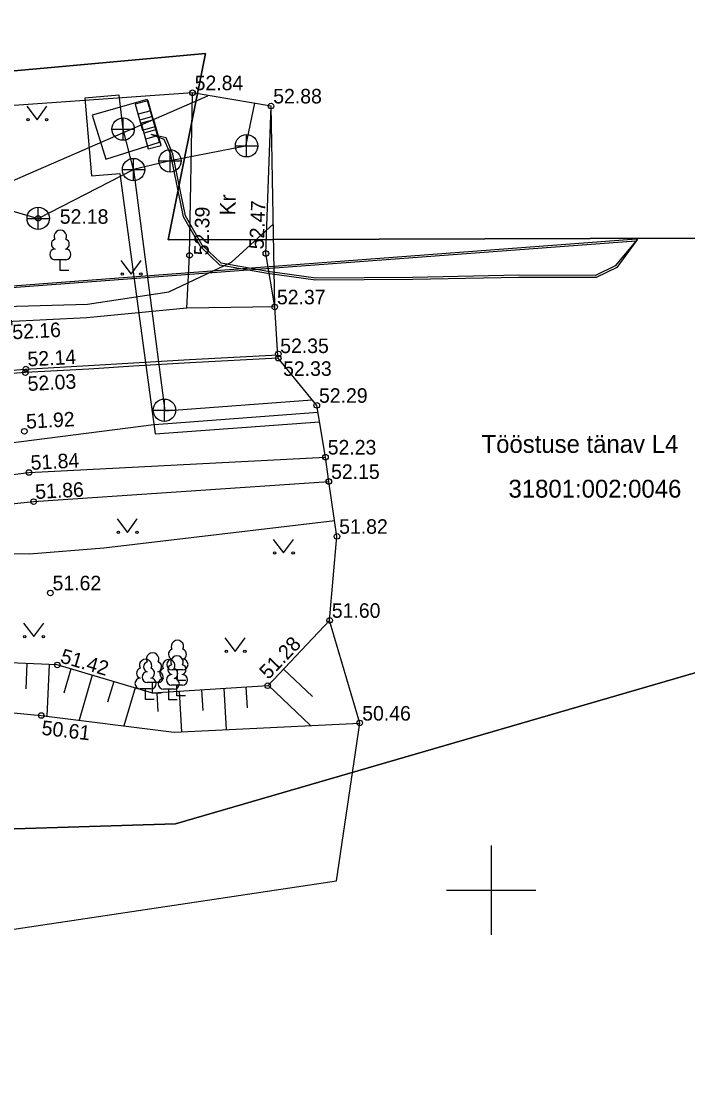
# Model space of a CAD drawing. Extents: x 542320 to 543602, y 6558748 to 6559969.
# Drawn here: x 543078.97 to 543108.8, y 6559791.38 to 6559838.87 of the extents above; entities that cross this region are included whole.
import ezdxf

# ---------------------------------------------------------------- set-up
doc = ezdxf.new("R2010")
doc.units = 0
for name, color, linetype in [('ELRAJATISMP', 7, 'Continuous'), ('HALJASTUS', 7, 'Continuous'), ('KKAEV', 7, 'Continuous'), ('KORGUS-EH2000', 7, 'Continuous'), ('KTRASS', 7, 'Continuous'), ('mootpiir', 7, 'Continuous'), ('MPKAABEL', 7, 'Continuous'), ('MPOHULIIN', 7, 'Continuous'), ('PIIR', 7, 'Continuous'), ('PUU', 7, 'Continuous'), ('RELJEEF', 7, 'Continuous'), ('SIOHULIIN', 7, 'Continuous'), ('SITRASS', 7, 'Continuous'), ('TEE', 7, 'Continuous'), ('VEEKOGU', 7, 'Continuous'), ('VORK', 7, 'Continuous'), ('VTRASS', 7, 'Continuous')]:
    doc.layers.add(name, color=color, linetype=linetype)

# ---------------------------------------------------------------- blocks, each defined once
blk = doc.blocks.new('VKORIS')
for p, q in [((0, 4), (0, -4)), ((-4, 0), (4, 0))]:
    blk.add_line(p, q)
blk = doc.blocks.new('KAKAEV')
for p, q in [((0, -1), (0, 1)), ((-1, 0), (1, 0))]:
    blk.add_line(p, q)
blk.add_circle((0, 0), 1)
blk = doc.blocks.new('LEHTP1')
for p, q in [((0.48, 0.95), (-0.48, 0.95)), ((0, 0), (0, 0.95)), ((0.76, 0), (0, 0))]:
    blk.add_line(p, q)
for centre, radius, start, end in [((0, 3.04), 0.554, 332.5799, 207.4201), ((-0.475, 1.425), 0.475, 90.0016, 269.3953), ((-0.34, 2.345), 0.465, 109.02174, 253.14154), ((0.34, 2.345), 0.465, 286.85082, 70.98591), ((0.475, 1.425), 0.475, 270.6047, 89.9984)]:
    blk.add_arc(centre, radius, start, end)
blk = doc.blocks.new('MURU')
for p, q in [((-0.927, 1.213), (0, 0)), ((0, 0), (0.891, 1.213))]:
    blk.add_line(p, q)
for centre in [(-0.802, 0), (0.856, 0)]:
    blk.add_circle(centre, 0.11)
blk = doc.blocks.new('ELKAPP')
for p, q in [((1.195, 0.597), (-1.195, 0.597)), ((-1.195, 0.597), (-1.195, -0.597)), ((-0.271, 0.597), (-0.271, -0.597)), ((0.271, 0.597), (0.271, -0.597)), ((1.195, -0.597), (1.195, 0.597)), ((-1.195, -0.597), (1.195, -0.597))]:
    blk.add_line(p, q)
blk = doc.blocks.new('RING02')
blk.add_circle((0, 0), 0.25)

msp = doc.modelspace()

# ---------------------------------------------------------------- linework, layer by layer
at = {"layer": 'KTRASS'}
for points in [[(543083.528, 6559834.046), (543083.349, 6559835.564), (543081.823, 6559835.431), (543082.115, 6559831.951), (543083.389, 6559832.057), (543084.964, 6559820.411), (543092.319, 6559820.95)], [(543089.402, 6559835.202), (543089.01, 6559833.277)], [(543066.724, 6559833.829), (543079.729, 6559830.052), (543083.997, 6559832.232)], [(543083.997, 6559832.232), (543083.528, 6559834.046)], [(543089.01, 6559833.277), (543085.628, 6559832.625)], [(543085.628, 6559832.625), (543083.997, 6559832.232)], [(543083.997, 6559832.232), (543085.402, 6559821.439)], [(543085.402, 6559821.439), (543091.987, 6559821.939)]]:
    msp.add_lwpolyline(points, dxfattribs=at)
at = {"layer": 'mootpiir'}
msp.add_lwpolyline([(543090.147, 6559835.076), (543086.631, 6559835.669), (543046.075, 6559832.791), (542960.087, 6559816.316), (542958.508, 6559813.972), (542958.352, 6559813.615), (542958.072, 6559811.407), (542958.097, 6559811.262), (542958.667, 6559807.427), (542958.816, 6559803.633), (542958.4, 6559802.481), (542958.245, 6559799.726), (542966.032, 6559797.567), (543032.743, 6559791.379), (543093.076, 6559800.414), (543094.129, 6559807.466), (543092.769, 6559812.064), (543093.098, 6559815.823), (543092.736, 6559818.278), (543092.585, 6559819.369), (543092.195, 6559821.683), (543090.475, 6559823.796), (543090.459, 6559823.908), (543090.312, 6559826.089)], close=True, dxfattribs=at)
at = {"layer": 'MPKAABEL'}
for points in [[(543106.54, 6559829.12), (543105.62, 6559827.85), (543104.69, 6559827.4), (543101.23, 6559827.41), (543096.5, 6559827.31), (543092.14, 6559827.28), (543089.99, 6559827.58), (543087.86, 6559827.95), (543086.99, 6559828.79), (543086.23, 6559830.12), (543085.66, 6559832.9), (543085.37, 6559833.58), (543084.79, 6559833.81)], [(543106.54, 6559829.12), (543105.55, 6559827.93), (543104.67, 6559827.5), (543101.23, 6559827.51), (543096.5, 6559827.41), (543092.15, 6559827.38), (543090.01, 6559827.68), (543087.91, 6559828.04), (543087.07, 6559828.85), (543086.32, 6559830.16), (543085.76, 6559832.93), (543085.45, 6559833.66), (543084.79, 6559833.81)]]:
    msp.add_lwpolyline(points, dxfattribs=at)
at = {"layer": 'MPOHULIIN'}
msp.add_lwpolyline([(543065.505, 6559826.048), (543106.507, 6559829.132)], dxfattribs=at)
at = {"layer": 'PIIR'}
for points in [[(543109.13, 6559904.85), (543125.66, 6559869.87), (543123.8, 6559868.51), (543128.91, 6559853.92), (543128.04, 6559829.23), (543085.54, 6559829.09), (543087.22, 6559837.42), (543076.83, 6559836.49), (543069.03, 6559887.03), (543109.13, 6559904.85)], [(543110.35, 6559810.08), (543085.87, 6559802.96), (543074.33, 6559802.6), (543047.65, 6559805.6), (543029.51, 6559799.26), (543012.82, 6559798.86), (543001.44, 6559800.31), (542966.22, 6559801.72), (542946.49, 6559799.49), (542945.79, 6559811), (542995.62, 6559810.72), (543011.79, 6559810.61), (543078.56, 6559825.31), (543076.83, 6559836.49), (543087.22, 6559837.42), (543085.54, 6559829.09), (543128.04, 6559829.23)], [(543012.82, 6559798.86), (543029.51, 6559799.26), (543047.65, 6559805.6), (543074.33, 6559802.6), (543085.87, 6559802.96), (543110.35, 6559810.08)]]:
    msp.add_lwpolyline(points, dxfattribs=at)
at = {"layer": 'RELJEEF'}
for points in [[(543092.769, 6559812.064), (543089.999, 6559809.142), (543084.85, 6559808.813), (543080.585, 6559810.073), (543073.543, 6559810.368), (543068.572, 6559810.695), (543059.132, 6559808.528), (543057.697, 6559808.874), (543055.711, 6559810.294), (543052.162, 6559811.058), (543042.149, 6559807.07), (543028.907, 6559800.786), (543017.173, 6559800.875), (543003.671, 6559801.671), (542989.215, 6559802.013), (542980.978, 6559802.587), (542969.167, 6559801.941), (542958.4, 6559802.481)], [(543079.219, 6559810.13), (543079.172, 6559809.006)], [(543080.218, 6559810.088), (543080.122, 6559807.778)], [(543081.192, 6559809.894), (543080.872, 6559808.809)], [(543090.705, 6559809.887), (543092.003, 6559808.656)], [(543082.151, 6559809.61), (543081.557, 6559807.598)], [(543083.11, 6559809.327), (543082.836, 6559808.399)], [(543084.069, 6559809.044), (543083.568, 6559807.346)], [(543086.033, 6559808.889), (543086.149, 6559807.08)], [(543087.031, 6559808.952), (543087.09, 6559808.04)], [(543088.029, 6559809.016), (543088.147, 6559807.177)], [(543089.027, 6559809.08), (543089.087, 6559808.152)], [(543090.017, 6559809.161), (543091.918, 6559807.359)], [(543085.035, 6559808.825), (543085.089, 6559807.986)]]:
    msp.add_lwpolyline(points, dxfattribs=at)
at = {"layer": 'SIOHULIIN'}
for points in [[(542986.521, 6559827.98), (543065.505, 6559826.048), (543087.322, 6559835.539)], [(543065.564, 6559825.995), (543106.476, 6559829.043)]]:
    msp.add_lwpolyline(points, dxfattribs=at)
at = {"layer": 'SITRASS'}
for points in [[(543053.917, 6559829.286), (543053.974, 6559828.4), (543059.028, 6559827.021), (543065.55, 6559826.599), (543077.169, 6559826.084), (543081.941, 6559826.218), (543085.572, 6559826.758), (543088.386, 6559828.092), (543090.244, 6559829.795)], [(543078.354, 6559815.059), (543079.334, 6559815.049), (543082.664, 6559815.311), (543092.997, 6559816.527)]]:
    msp.add_lwpolyline(points, dxfattribs=at)
at = {"layer": 'TEE'}
for points in [[(543086.383, 6559826.03), (543086.502, 6559828.397), (543086.631, 6559835.669)], [(543082.751, 6559832.699), (543085.159, 6559833.466), (543084.609, 6559835.363), (543082.149, 6559834.671), (543082.751, 6559832.699)], [(543090.312, 6559826.089), (543089.919, 6559828.48), (543090.147, 6559835.076)], [(543090.312, 6559826.089), (543086.383, 6559826.03), (543081.905, 6559825.596), (543078.303, 6559825.425), (543074.1, 6559825.199), (543070.074, 6559824.663), (543067.487, 6559824.275), (543065.214, 6559823.846), (543059.834, 6559822.98), (543060.342, 6559820.61)], [(543090.467, 6559823.936), (543086.5, 6559823.721), (543083.992, 6559823.574), (543081.981, 6559823.449), (543079.149, 6559823.293), (543078.382, 6559823.232), (543074.353, 6559822.916), (543070.335, 6559822.452), (543067.933, 6559822.071), (543065.56, 6559821.631), (543060.801, 6559820.746), (543060.324, 6559820.64)], [(543090.475, 6559823.796), (543086.508, 6559823.581), (543084, 6559823.434), (543081.989, 6559823.309), (543079.158, 6559823.153), (543078.393, 6559823.092), (543074.367, 6559822.777), (543070.354, 6559822.313), (543067.957, 6559821.933), (543065.586, 6559821.493), (543060.829, 6559820.609), (543060.355, 6559820.503)], [(542958.816, 6559803.633), (542969.162, 6559804.651), (542980.925, 6559804.056), (542987.926, 6559803.597), (542997.513, 6559803.059), (543007.107, 6559803.04), (543017.723, 6559803.474), (543028.051, 6559804.793), (543037.828, 6559808.06), (543042.163, 6559809.918), (543050.261, 6559812.635), (543059.043, 6559815.346), (543068.835, 6559817.386), (543079.318, 6559818.681), (543092.585, 6559819.369)], [(542997.513, 6559803.059), (543007.066, 6559802.483), (543017.906, 6559802.775), (543028.213, 6559804.2), (543038.057, 6559807.69), (543042.598, 6559809.18), (543050.432, 6559811.965), (543059.255, 6559814.566), (543068.982, 6559816.272), (543079.524, 6559817.38), (543092.736, 6559818.278)]]:
    msp.add_lwpolyline(points, dxfattribs=at)
at = {"layer": 'VEEKOGU'}
msp.add_lwpolyline([(542958.245, 6559799.726), (542969.193, 6559799.837), (542980.767, 6559800.499), (542989.253, 6559800.672), (543003.747, 6559800.309), (543017.23, 6559799.73), (543028.875, 6559799.639), (543042.762, 6559805.872), (543054.415, 6559808.402), (543057.212, 6559806.164), (543069.386, 6559808.821), (543079.867, 6559807.81), (543085.814, 6559807.064), (543094.129, 6559807.466)], dxfattribs=at)
at = {"layer": 'VTRASS'}
for points in [[(543092.248, 6559821.369), (543084.938, 6559820.819), (543084.909, 6559820.815)], [(543084.909, 6559820.815), (543050.322, 6559816.388), (543018.303, 6559809.334), (542995.998, 6559810.646), (542958.256, 6559810.221)]]:
    msp.add_lwpolyline(points, dxfattribs=at)

# ---------------------------------------------------------------- block references
at = {"layer": 'ELRAJATISMP', "xscale": 0.5, "yscale": 0.5, "rotation": -74.41800004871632}
for p in [(543084.522, 6559834.658), (543084.782, 6559833.81)]:
    msp.add_blockref('ELKAPP', p, dxfattribs=at)
at = {"layer": 'HALJASTUS', "xscale": 0.5, "yscale": 0.5}
for p in [(543079.678, 6559834.464), (543083.895, 6559827.561), (543083.72, 6559816.004), (543090.71, 6559815.083), (543079.529, 6559811.338), (543088.549, 6559810.677)]:
    msp.add_blockref('MURU', p, dxfattribs=at)
at = {"layer": 'KKAEV', "xscale": 0.5, "yscale": 0.5}
for p in [(543083.528, 6559834.046), (543089.054, 6559833.298), (543085.628, 6559832.625), (543083.997, 6559832.232), (543079.729, 6559830.052), (543085.377, 6559821.468)]:
    msp.add_blockref('KAKAEV', p, dxfattribs=at)
at = {"layer": 'KORGUS-EH2000', "xscale": 0.5, "yscale": 0.5}
for p in [(543086.631, 6559835.669), (543090.147, 6559835.076), (543079.729, 6559830.052), (543086.502, 6559828.397), (543089.919, 6559828.48), (543090.312, 6559826.089), (543090.475, 6559823.985), (543090.475, 6559823.796), (543079.158, 6559823.153), (543079.18, 6559823.311), (543092.195, 6559821.683), (543079.113, 6559820.525), (543092.585, 6559819.369), (543079.318, 6559818.681), (543092.736, 6559818.278), (543079.524, 6559817.38), (543093.098, 6559815.823), (543080.273, 6559813.294), (543092.769, 6559812.064), (543080.585, 6559810.073), (543089.999, 6559809.142), (543079.867, 6559807.81), (543094.114, 6559807.477)]:
    msp.add_blockref('RING02', p, dxfattribs=at)
at = {"layer": 'PUU', "xscale": 0.5, "yscale": 0.5}
for p in [(543080.72, 6559827.725), (543085.959, 6559809.378), (543084.535, 6559808.528), (543084.85, 6559808.813), (543085.572, 6559808.514), (543085.94, 6559808.689)]:
    msp.add_blockref('LEHTP1', p, dxfattribs=at)
at = {"layer": 'VORK', "xscale": 0.5, "yscale": 0.5}
msp.add_blockref('VKORIS', (543100, 6559800), dxfattribs=at)

# ---------------------------------------------------------------- texts
at = {"layer": 'KORGUS-EH2000'}
for s, p in [('52.84', (543086.731, 6559835.786)), ('52.88', (543090.247, 6559835.193)), ('52.18', (543080.697, 6559829.808)), ('52.37', (543090.412, 6559826.206)), ('52.35', (543090.559, 6559824.025)), ('52.33', (543090.688, 6559823.005)), ('52.29', (543092.295, 6559821.8)), ('52.23', (543092.685, 6559819.486)), ('52.15', (543092.836, 6559818.395)), ('51.82', (543093.198, 6559815.94)), ('51.62', (543080.373, 6559813.411)), ('51.60', (543092.869, 6559812.181)), ('50.46', (543094.229, 6559807.583))]:
    msp.add_text(s, height=0.65, dxfattribs=at).set_placement(p)
for s, rotation, p in [('52.47', 87.5335, (543089.817, 6559828.656)), ('52.39', 88.6145, (543087.353, 6559828.39)), ('52.16', 2.9274, (543078.587, 6559824.64)), ('52.14', 2.9274, (543079.269, 6559823.427)), ('52.03', 2.9274, (543079.273, 6559822.328)), ('51.92', 2.9274, (543079.202, 6559820.641)), ('51.84', 2.9274, (543079.407, 6559818.797)), ('51.86', 2.9274, (543079.613, 6559817.496)), ('51.28', 46.231, (543090.03, 6559809.389)), ('51.42', 343.6293, (543080.68, 6559810.19)), ('50.61', 353.2479, (543079.857, 6559806.952))]:
    msp.add_text(s, height=0.65, rotation=rotation, dxfattribs=at).set_placement(p)
at = {"layer": 'PIIR'}
for s, p in [('Tööstuse tänav L4', (543099.569, 6559819.559)), ('31801:002:0046', (543100.775, 6559817.556))]:
    msp.add_text(s, height=0.8, dxfattribs=at).set_placement(p)
at = {"layer": 'TEE'}
msp.add_text('Kr', height=0.7, rotation=89.2581, dxfattribs=at).set_placement((543088.552, 6559830.177))

doc.saveas('drawing.dxf')
